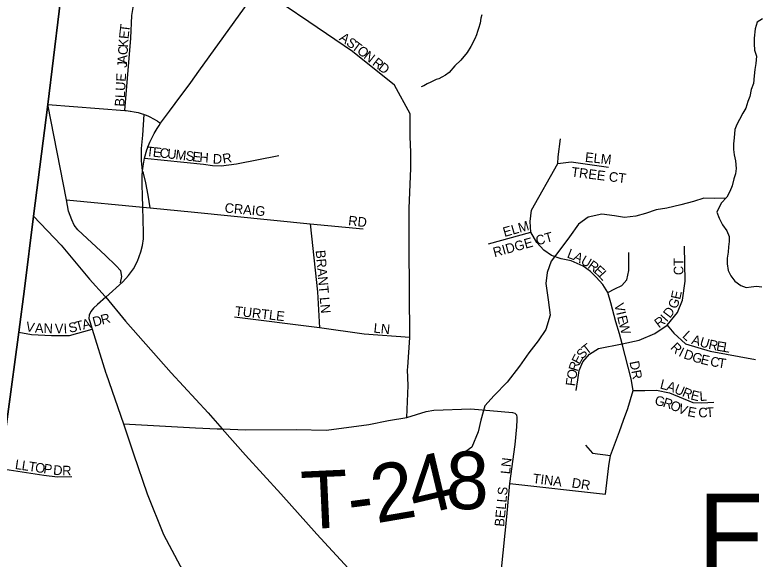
# Model space of a CAD drawing. Extents: x 1310247 to 1664935, y 235267 to 584339.
# Drawn here: x 1455647 to 1459518, y 408689 to 411521 of the extents above; entities that cross this region are included whole.
import ezdxf

# ---------------------------------------------------------------- set-up
doc = ezdxf.new("R2010")
doc.units = 0
for name, color, linetype in [('GM_X_Adjacent_County', 7, 'Continuous'), ('GM_X_County', 7, 'Continuous'), ('GM_X_County_Road', 7, 'Continuous'), ('GM_X_County_ROW', 7, 'Continuous'), ('GM_X_Minor_River', 7, 'Continuous'), ('GM_X_State_Route', 7, 'Continuous'), ('GM_X_Township', 7, 'Continuous'), ('GM_X_Township_Road', 7, 'Continuous'), ('GM_X_Township_Road_Text', 7, 'Continuous'), ('GM_X_Township_ROW', 7, 'Continuous'), ('GM_X_Township_Subdivision', 7, 'Continuous'), ('GM_X_Township_Subdivision_Text', 7, 'Continuous'), ('GM_X_Unincorporated_Text', 7, 'Continuous')]:
    doc.layers.add(name, color=color, linetype=linetype)

msp = doc.modelspace()

# ---------------------------------------------------------------- linework, layer by layer
at = {"layer": 'GM_X_Adjacent_County'}
msp.add_lwpolyline([(1457514.1, 424598.8), (1456288.4, 414870.2), (1456150.3, 413755.9), (1455965.4, 412270.1), (1455818.5, 411054.1), (1455743.6, 410473.9), (1455696.6, 410094.7), (1455666.7, 409869.1), (1455572.5, 409158), (1455355.4, 407518.9), (1455298.5, 407089), (1455188.8, 406136.8), (1455061.2, 405297.6), (1454959.8, 404514.8), (1454480.8, 400915.8), (1454072.9, 397836.5), (1453769.5, 395544.2)], dxfattribs=at)
at = {"layer": 'GM_X_County'}
msp.add_lwpolyline([(1453769.5, 395544.2), (1454072.9, 397836.5), (1454480.8, 400915.8), (1454959.8, 404514.8), (1455061.2, 405297.6), (1455188.8, 406136.8), (1455298.5, 407089), (1455355.4, 407518.9), (1455572.5, 409158), (1455666.7, 409869.1), (1455696.6, 410094.7), (1455743.6, 410473.9), (1455818.5, 411054.1), (1455965.4, 412270.1), (1456150.3, 413755.9), (1456288.4, 414870.2), (1457514.1, 424598.8)], dxfattribs=at)
at = {"layer": 'GM_X_County_Road'}
for points in [[(1456604, 411227.6), (1456917.4, 411665), (1457433.4, 412421.3), (1457679.5, 412793.8), (1457748.7, 412898.3), (1457872.9, 413091.5), (1457953.8, 413219.3), (1458061.4, 413383.9), (1458128.3, 413490.7), (1458183.5, 413580), (1458269.2, 413766.6), (1458482, 414269.6)], [(1456119.1, 410052.7), (1456207.5, 410131.3), (1456237.8, 410164), (1456263.7, 410200.3), (1456284.8, 410239.6), (1456302.7, 410287.8), (1456310.6, 410321.5), (1456315.3, 410356.4), (1456316.4, 410388.5), (1456312.5, 410519.6), (1456310.5, 410581.3), (1456308.8, 410636.4), (1456308.9, 410685), (1456311.2, 410709.2), (1456313.5, 410733.3), (1456321.2, 410775), (1456333.6, 410818.7), (1456348.9, 410858.9), (1456371.1, 410904.2), (1456386.1, 410929.6), (1456396.7, 410945.5), (1456404.9, 410957.4), (1456451.8, 411019.9), (1456481.1, 411060.3), (1456562.2, 411169.4), (1456604, 411227.6)], [(1455914.3, 410558.1), (1455818.5, 411054.1)], [(1455818.5, 411054.1), (1456218.9, 411023.4), (1456224.7, 411023), (1456246.2, 411020.8), (1456248.8, 411020.3), (1456267.5, 411017.3), (1456288.5, 411012.4), (1456292.8, 411011.2), (1456309.2, 411006.3), (1456316.1, 411003.8), (1456319.4, 411002.6), (1456329.5, 410998.9), (1456340.9, 410994), (1456349.3, 410990.3), (1456368.5, 410980.5), (1456387.1, 410969.5), (1456388.8, 410968.4), (1456404.9, 410957.4)], [(1456119.1, 410052.7), (1456077, 410014.5), (1456055.3, 409994.3), (1456041.4, 409977), (1456032.4, 409957.5), (1456031, 409940.2), (1456035.8, 409924.7), (1456047.9, 409885.3), (1456120.3, 409656.9)], [(1456120.3, 409656.9), (1456121.2, 409653.8), (1456211.7, 409392.8), (1456264.3, 409237), (1456334.6, 409028.1), (1456420.2, 408817.7), (1456505.8, 408654.7), (1456554.4, 408564.1), (1456623.7, 408460.7), (1456690.5, 408359.8), (1456848.3, 408134.9), (1456991.5, 408001.6), (1457107.6, 407905), (1457406.9, 407671.3), (1457589, 407523.7), (1457703.4, 407430.2), (1457832.8, 407323.5), (1457953.8, 407263)]]:
    msp.add_lwpolyline(points, dxfattribs=at)
at = {"layer": 'GM_X_County_ROW'}
msp.add_lwpolyline([(1456196.5, 410126.9), (1456202.8, 410159.6), (1456197.2, 410189.1), (1456172.6, 410217.4), (1456117.4, 410269.5), (1455973.3, 410401.7), (1455954.7, 410426.4), (1455943.2, 410454.3), (1455925.1, 410498.9), (1455914.3, 410558.1)], dxfattribs=at)
at = {"layer": 'GM_X_Minor_River'}
for points in [[(1458075.1, 411522), (1458070.8, 411504), (1458066.3, 411478), (1458057.8, 411450), (1458053.6, 411434), (1458047.3, 411418), (1458038.9, 411396.1)], [(1459535, 411501.3), (1459508.6, 411483.9), (1459497.6, 411448), (1459492.4, 411400), (1459491.6, 411369.9), (1459494.8, 411337.7), (1459503.9, 411305.4), (1459501, 411267.3), (1459496.2, 411237.3), (1459493.3, 411203.3), (1459488.3, 411163.2), (1459477.5, 411133.4), (1459470.5, 411095.5), (1459459.8, 411069.6), (1459449, 411035.8), (1459434.3, 411010.1), (1459415.4, 410976.5), (1459402.7, 410950.7), (1459392.1, 410924.9), (1459388.9, 410880.8), (1459384.2, 410850.8), (1459385.4, 410820.7), (1459388.7, 410792.5), (1459395.9, 410762.2), (1459398.8, 410722), (1459396.1, 410693.9), (1459387.4, 410668.1), (1459378.5, 410632.2), (1459365.7, 410602.4), (1459351, 410572.7), (1459320.1, 410541.4), (1459298.9, 410493.8), (1459310.1, 410463.3), (1459327.2, 410428.8), (1459350.5, 410398), (1459361.7, 410367.6), (1459363, 410341.5), (1459358.3, 410313.5), (1459357.6, 410285.4), (1459352.8, 410255.5), (1459352, 410225.4), (1459357.1, 410191.1), (1459370.4, 410162.7), (1459391.7, 410136), (1459423.1, 410113.1), (1459450.9, 410102.3), (1459477, 410105.7), (1459505.1, 410108.9), (1459533, 410106.2)], [(1458038.9, 411396.1), (1458018.1, 411356.3), (1457999.5, 411324.5), (1457966.7, 411284.9), (1457936.1, 411255.3), (1457905.5, 411221.7), (1457887.2, 411208), (1457866.9, 411196.3), (1457852.7, 411188.5), (1457838.6, 411184.7), (1457810.3, 411171.1), (1457792, 411161.4), (1457773.8, 411151.7), (1457759.6, 411145.9)], [(1459345, 410566.7), (1459287.3, 410564.9), (1459231.2, 410568.1), (1459176.7, 410549.1), (1459110.2, 410532.4), (1459037.7, 410515.8), (1458983.4, 410506.8), (1458926.9, 410487.9), (1458876.4, 410472.8), (1458818.1, 410466), (1458766.2, 410475), (1458700.2, 410484.4), (1458629.7, 410467.8), (1458578.9, 410432.6), (1458531.4, 410365.4), (1458481.9, 410298.1), (1458436.6, 410238.8), (1458415.4, 410181), (1458408.3, 410123), (1458420.6, 410038.4), (1458431, 409957.9), (1458409.5, 409884.1), (1458368.2, 409824.7), (1458320.8, 409761.5), (1458271.3, 409692.2), (1458207.5, 409609.2), (1458140, 409540.3), (1458090.8, 409487.1), (1458071.2, 409411.2), (1458056, 409351.3), (1458024.3, 409271.7), (1457936.9, 409209.2)]]:
    msp.add_lwpolyline(points, dxfattribs=at)
at = {"layer": 'GM_X_State_Route'}
msp.add_lwpolyline([(1455743.6, 410473.9), (1455887.7, 410322.7), (1456035, 410145.9), (1456116.1, 410056), (1456119.1, 410052.7), (1456222.5, 409927.1), (1456459.9, 409658.4), (1456651.3, 409449.3), (1456725.4, 409366.1), (1456846.4, 409230.2), (1457030, 409029.4), (1457217.3, 408818.5), (1457401.1, 408619.7)], dxfattribs=at)
at = {"layer": 'GM_X_Township'}
msp.add_lwpolyline([(1453769.5, 395544.2), (1454072.9, 397836.5), (1454480.8, 400915.8), (1454959.8, 404514.8), (1455061.2, 405297.6), (1455188.8, 406136.8), (1455298.5, 407089), (1455355.4, 407518.9), (1455572.5, 409158), (1455666.7, 409869.1), (1455696.6, 410094.7), (1455743.6, 410473.9), (1455818.5, 411054.1), (1455965.4, 412270.1), (1456150.3, 413755.9), (1456288.4, 414870.2), (1457514.1, 424598.8)], dxfattribs=at)
at = {"layer": 'GM_X_Township_Road'}
for points in [[(1456699.6, 409367.2), (1456725.4, 409366.1), (1456847.6, 409360.9), (1457109.7, 409363.6), (1457267.7, 409360.5), (1457488.4, 409390.1), (1457589.4, 409410.4), (1457685.4, 409426.1), (1457785.8, 409456.4), (1457826, 409463.6), (1458018, 409471.4), (1458235.2, 409452), (1458247.5, 409448.5), (1458257.7, 409438.3)], [(1456211.7, 409392.8), (1456585.7, 409372.1), (1456699.6, 409367.2)]]:
    msp.add_lwpolyline(points, dxfattribs=at)
at = {"layer": 'GM_X_Township_ROW'}
msp.add_lwpolyline([(1456349.9, 410516.1), (1456340.8, 410582.3), (1456328.3, 410646.6), (1456315, 410696.9), (1456311.2, 410709.2), (1456305.2, 410763.9), (1456305.9, 410826.1), (1456312.2, 410895.3), (1456319.4, 411002.6)], dxfattribs=at)
at = {"layer": 'GM_X_Township_Subdivision'}
for points in [[(1456218.9, 411023.4), (1456249, 411399.4), (1456255.7, 411518.2), (1456265, 411581), (1456305.1, 411634.4), (1456564.5, 411991.3), (1456916.1, 412455)], [(1457175, 411484.8), (1457053.2, 411567.7), (1456917.4, 411665)], [(1457702.6, 410892.6), (1457702.6, 411006.4), (1457620.7, 411155.1), (1457403, 411329.8), (1457175, 411484.8)], [(1457690.6, 409688), (1457700.5, 409842.2), (1457698.3, 410318.7), (1457698.3, 410514.9), (1457707, 410721.8), (1457707, 410805.9), (1457702.6, 410885.7), (1457702.6, 410892.6)], [(1458718.5, 409026), (1458735.7, 409173.6), (1458745.3, 409227.2), (1458791.7, 409353.1), (1458813.5, 409412.6), (1458835.2, 409472.1), (1458862.6, 409567), (1458852.4, 409626.5), (1458805.4, 409808.4), (1458792, 409861.4), (1458773.1, 409924.5), (1458747, 410021.7), (1458731.2, 410077.1), (1458705.5, 410117.7), (1458670.8, 410156.3), (1458640.2, 410186), (1458602.6, 410212.7), (1458540.2, 410241.4), (1458487.7, 410252.3), (1458437.3, 410269.1), (1458397.7, 410296.9), (1458361.1, 410336.4), (1458329.8, 410390.8), (1458326.4, 410446.3), (1458333.3, 410504.7), (1458470.7, 410747.4), (1458473.2, 410782.4), (1458485.7, 410876.2)], [(1456321.2, 410775), (1456628.1, 410745), (1456675.4, 410736.9), (1456720.6, 410734.7), (1456799.4, 410745.5), (1457020.3, 410789.7)], [(1458470.7, 410747.4), (1458540.7, 410756.2), (1458734.5, 410728.7)], [(1455914.3, 410558.1), (1456312.5, 410519.6), (1456349.9, 410516.1), (1456580.6, 410495.2), (1457182.8, 410433.5), (1457459.1, 410407.2)], [(1457182.8, 410433.5), (1457208.8, 410191.9), (1457220.5, 410079.2), (1457230.6, 409892.2)], [(1458109.6, 410329.5), (1458329.8, 410390.8)], [(1458566.4, 409567), (1458575.5, 409621.9), (1458582.4, 409671.1), (1458600.7, 409715.7), (1458636.2, 409754.6), (1458681.9, 409784.4), (1458805.4, 409808.4), (1458895, 409828.5), (1458975.9, 409862.1), (1459039.9, 409906.8), (1459093.7, 409973.1), (1459120, 410037.1), (1459133.7, 410135.5), (1459129.2, 410317.4)], [(1458731.2, 410077.1), (1458766.8, 410095.9), (1458803.5, 410112.8), (1458829.2, 410142.5), (1458840.1, 410190.9), (1458840.1, 410285)], [(1457700.5, 409842.2), (1457463.9, 409859.5), (1457230.6, 409892.2), (1456788.6, 409947.9)], [(1455666.7, 409869.1), (1455732.8, 409858.6), (1455836.7, 409852), (1455930, 409853.2), (1456047.9, 409885.3)], [(1459039.9, 409906.8), (1459074.2, 409864.4), (1459134.9, 409809.5), (1459263, 409771.8), (1459499.8, 409727.2)], [(1457685.4, 409426.1), (1457691.9, 409592.2), (1457689.7, 409674.1), (1457690.6, 409688)], [(1458862.6, 409567), (1458923.3, 409567), (1458983.9, 409568.2), (1459051.4, 409554.5), (1459172.6, 409504.1), (1459219.5, 409501.8), (1459283.3, 409506.4)], [(1458079.1, 407859.9), (1458089.9, 407999.7), (1458126, 408218.4), (1458177.5, 408637.1), (1458206.1, 408909.3), (1458222.1, 409082.1), (1458248.4, 409285.6), (1458257.7, 409376.5), (1458259.5, 409414.1), (1458260.3, 409428.2), (1458257.7, 409438.3)], [(1458614.4, 409281.1), (1458651.1, 409239.9), (1458745.3, 409227.2)], [(1455942.3, 409116.2), (1455867.6, 409114.9), (1455796.6, 409123.9), (1455572.5, 409158)], [(1458222.1, 409082.1), (1458718.5, 409026)]]:
    msp.add_lwpolyline(points, dxfattribs=at)

# ---------------------------------------------------------------- texts
at = {"layer": 'GM_X_Township_Road_Text'}
for s, rotation, p in [('4', 13.3081, (1457727.8, 408909.9)), ('8', 359.2764, (1457886.9, 408950)), ('2', 9.7328, (1457527.1, 408874.8)), ('T', 2.6517, (1457142.1, 408844)), ('-', 7.5659, (1457393.8, 408856.9))]:
    msp.add_text(s, height=300, rotation=rotation, dxfattribs=at).set_placement(p)
at = {"layer": 'GM_X_Township_Subdivision_Text'}
for s, rotation, p in [('T', 83.346, (1456241.1, 411428.7)), ('E', 84.3084, (1456237.7, 411393.9)), ('K', 86.3691, (1456234.9, 411350.5)), ('A', 324.1092, (1457330.5, 411393)), ('S', 324.1195, (1457366.2, 411367.2)), ('C', 86.6891, (1456232.6, 411311)), ('T', 323.1028, (1457394.5, 411346.7)), ('O', 322.0196, (1457422.5, 411325.8)), ('N', 321.9103, (1457457.2, 411298.7)), ('J', 86.7208, (1456228.9, 411245.1)), ('A', 86.6977, (1456230.1, 411267.1)), ('R', 321.9014, (1457502.2, 411263.4)), ('D', 321.9248, (1457533.3, 411239)), ('BLUE', 86.8158, (1456215.7, 411042.7)), ('T', 353.4849, (1456327.4, 410787.6)), ('E', 353.5103, (1456362.4, 410783.6)), ('C', 353.4774, (1456397.3, 410779.6)), ('U', 353.4914, (1456436.7, 410775.1)), ('M', 353.4968, (1456480.4, 410770.1)), ('S', 353.4849, (1456532.9, 410764.1)), ('E', 353.4956, (1456567.9, 410760.1)), ('H', 355.8382, (1456605.1, 410755.9)), ('D', 357.4421, (1456675.3, 410747.9)), ('R', 9.6136, (1456730.7, 410746.7)), ('ELM', 354.0969, (1458610.8, 410756.7)), ('TREE CT', 352.875, (1458538.8, 410680.2)), ('CRAIG', 354.6883, (1456736.3, 410492.8)), ('RD', 353.6638, (1457378.9, 410426.7)), ('ELM', 15.9444, (1458193.7, 410364.8)), ('RIDGE CT', 15.3359, (1458141.7, 410259.9)), ('BRANT LN', 274.9704, (1457211.1, 410294.9)), ('L', 339.2233, (1458515.5, 410259.3)), ('A', 333.9334, (1458547.3, 410247.3)), ('U', 330.0708, (1458586.1, 410228.4)), ('R', 324.0869, (1458623, 410207.2)), ('CT', 90, (1459124.1, 410166.6)), ('E', 318.3438, (1458654.1, 410184.8)), ('L', 312.7001, (1458679.5, 410162.3)), ('E', 77.7279, (1459107.4, 410036.9)), ('G', 68.2462, (1459088.4, 409987.4)), ('TURTLE', 353.5408, (1456789.3, 409956)), ('V', 283.2994, (1458764.2, 410014.7)), ('D', 52.4089, (1459054.1, 409939.4)), ('R', 14.8054, (1456100.5, 409908.9)), ('I', 283.3203, (1458774.4, 409971.9)), ('I', 48.5875, (1459037.3, 409920.1)), ('V', 349.8477, (1455700.2, 409876.3)), ('S', 11.8852, (1455931.5, 409866.2)), ('T', 14.7212, (1455968.5, 409874.1)), ('A', 14.8023, (1456002.6, 409883)), ('D', 14.7883, (1456058, 409897.7)), ('E', 283.314, (1458779.4, 409950.5)), ('W', 284.5215, (1458787.8, 409915.2)), ('R', 36.3113, (1458996.7, 409888.8)), ('A', 356.9416, (1455750.2, 409867.8)), ('N', 358.0337, (1455795.2, 409865.4)), ('V', 0.1279, (1455854.4, 409863.7)), ('I', 3.2203, (1455901.3, 409863.9)), ('LN', 353.9934, (1457510.9, 409868)), ('L', 317.3385, (1459115.3, 409846)), ('A', 344.124, (1459163.2, 409809.8)), ('U', 343.0098, (1459205.3, 409797.8)), ('T', 38.1649, (1458621.5, 409750.6)), ('R', 314.0901, (1459053.3, 409786.8)), ('R', 347.4528, (1459251.5, 409783.9)), ('E', 350.0971, (1459292.6, 409774.8)), ('L', 350.2245, (1459327.4, 409768.7)), ('S', 46.1013, (1458598.4, 409726.4)), ('I', 333.4429, (1459095.6, 409747.5)), ('D', 341.13, (1459122.1, 409734.9)), ('G', 343.2176, (1459165.6, 409720)), ('E', 61.8954, (1458584, 409698.3)), ('E', 346.3898, (1459210.6, 409706.5)), ('C', 349.5494, (1459260.7, 409694.9)), ('T', 351.1777, (1459301.2, 409687.4)), ('R', 72.6865, (1458573.1, 409662.8)), ('DR', 281.3036, (1458843.5, 409715.2)), ('O', 79.4058, (1458565.4, 409621.1)), ('F', 82.4378, (1458560.9, 409586.9)), ('L', 345.6722, (1458999.3, 409577.4)), ('A', 341.2195, (1459032.4, 409568.9)), ('U', 337.4844, (1459073.2, 409555.1)), ('R', 337.7697, (1459114.1, 409538.1)), ('G', 348.0472, (1458972.3, 409491.9)), ('E', 346.4294, (1459158.6, 409520.6)), ('L', 4.5188, (1459210, 409511)), ('R', 341.7724, (1459014, 409483.1)), ('O', 337.1027, (1459050.6, 409471.1)), ('V', 337.5624, (1459091.5, 409453.8)), ('E', 349.2563, (1459142.8, 409433.9)), ('C', 1.9768, (1459202.7, 409425.7)), ('T', 3.8681, (1459244.1, 409427.2)), ('L', 351.4179, (1455645, 409158.5)), ('L', 351.4386, (1455679.8, 409153.2)), ('T', 351.448, (1455714.6, 409148)), ('O', 351.4217, (1455749.4, 409142.7)), ('P', 351.4179, (1455792.9, 409136.2)), ('LN', 83.9946, (1458222.1, 409129.2)), ('D', 354.9248, (1455844.1, 409128.6)), ('R', 359.9466, (1455892.7, 409124.4)), ('TINA', 353.0919, (1458338.2, 409084.6)), ('DR', 351.0215, (1458540.9, 409062.5)), ('BELLS', 84.5579, (1458191.3, 408856))]:
    msp.add_text(s, height=50, rotation=rotation, dxfattribs=at).set_placement(p)
at = {"layer": 'GM_X_Unincorporated_Text'}
msp.add_text('Fernell', height=417, rotation=0, dxfattribs=at).set_placement((1459199.5, 408613.2))

doc.saveas('drawing.dxf')
